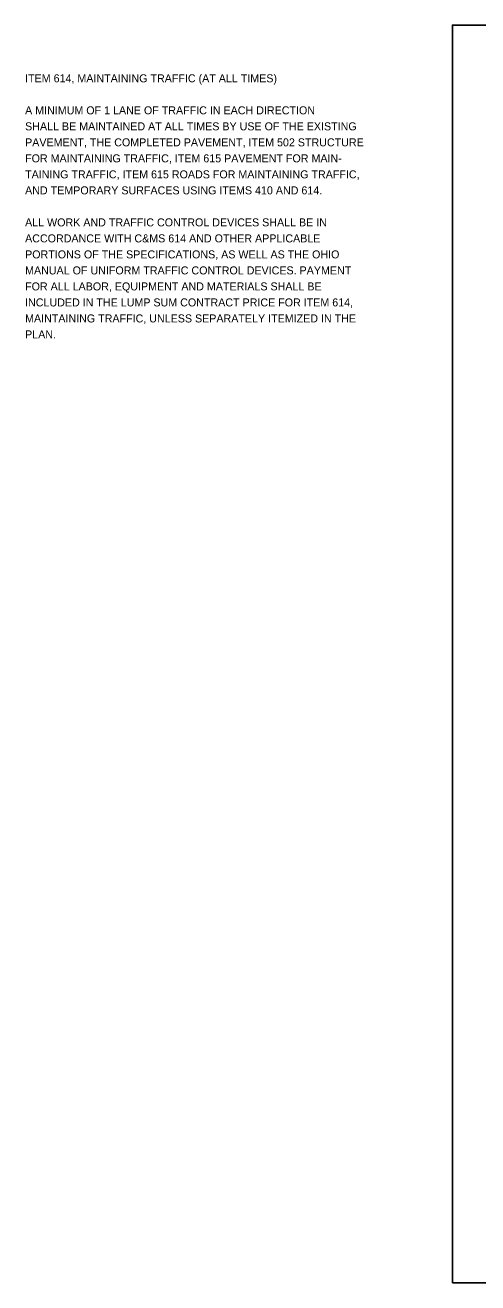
# Model space of a CAD drawing. Extents: x -7.5 to 34, y 0 to 22.
# Drawn here: x -7.48 to 0.45, y 0 to 22 of the extents above; entities that cross this region are included whole.
import ezdxf

# ---------------------------------------------------------------- set-up
doc = ezdxf.new("R2010")
doc.units = 0
for name, color, linetype in [('SH_Cut_Line', 7, 'Continuous'), ('SH_Data', 7, 'Continuous'), ('SH_Text', 7, 'Continuous')]:
    doc.layers.add(name, color=color, linetype=linetype)

msp = doc.modelspace()

# ---------------------------------------------------------------- linework, layer by layer
at = {"layer": 'SH_Cut_Line'}
msp.add_lwpolyline([(0, 0), (34, 0), (34, 22), (0, 22)], close=True, dxfattribs=at)
at = {"layer": 'SH_Data'}
msp.add_line((0, 0), (0, 0), dxfattribs=at)

# ---------------------------------------------------------------- texts
at = {"layer": 'SH_Text'}
for s, p in [('ITEM 614, MAINTAINING TRAFFIC (AT ALL TIMES)', (-7.48, 21)), ('A MINIMUM OF 1 LANE OF TRAFFIC IN EACH DIRECTION', (-7.48, 20.44)), ('SHALL BE MAINTAINED AT ALL TIMES BY USE OF THE EXISTING', (-7.48, 20.16)), ('PAVEMENT, THE COMPLETED PAVEMENT, ITEM 502 STRUCTURE', (-7.48, 19.88)), ('FOR MAINTAINING TRAFFIC, ITEM 615 PAVEMENT FOR MAIN-', (-7.48, 19.6)), ('TAINING TRAFFIC, ITEM 615 ROADS FOR MAINTAINING TRAFFIC,', (-7.48, 19.32)), ('AND TEMPORARY SURFACES USING ITEMS 410 AND 614.', (-7.48, 19.04)), ('ALL WORK AND TRAFFIC CONTROL DEVICES SHALL BE IN', (-7.48, 18.48)), ('ACCORDANCE WITH C&MS 614 AND OTHER APPLICABLE', (-7.48, 18.2)), ('PORTIONS OF THE SPECIFICATIONS, AS WELL AS THE OHIO', (-7.48, 17.92)), ('MANUAL OF UNIFORM TRAFFIC CONTROL DEVICES. PAYMENT', (-7.48, 17.64)), ('FOR ALL LABOR, EQUIPMENT AND MATERIALS SHALL BE', (-7.48, 17.36)), ('INCLUDED IN THE LUMP SUM CONTRACT PRICE FOR ITEM 614,', (-7.48, 17.08)), ('MAINTAINING TRAFFIC, UNLESS SEPARATELY ITEMIZED IN THE', (-7.48, 16.8)), ('PLAN.', (-7.48, 16.52))]:
    msp.add_text(s, height=0.14, dxfattribs=at).set_placement(p)

doc.saveas('drawing.dxf')
